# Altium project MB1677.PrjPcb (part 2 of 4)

## Sheet Arduino.SchDoc: Arduino
size A4; Date: Not used; ApprovedBy: Not used; CheckedBy: Not used; Author: Not used; CompanyName: STMicroelectronics; DrawnBy: Not used; Engineer: Not used; Organization: Not used; Address1: Not used; Address2: Not used; Address3: Not used; Address4: Not used; DocumentNumber: 11; Revision: Not used; SheetNumber: 11; SheetTotal: 15
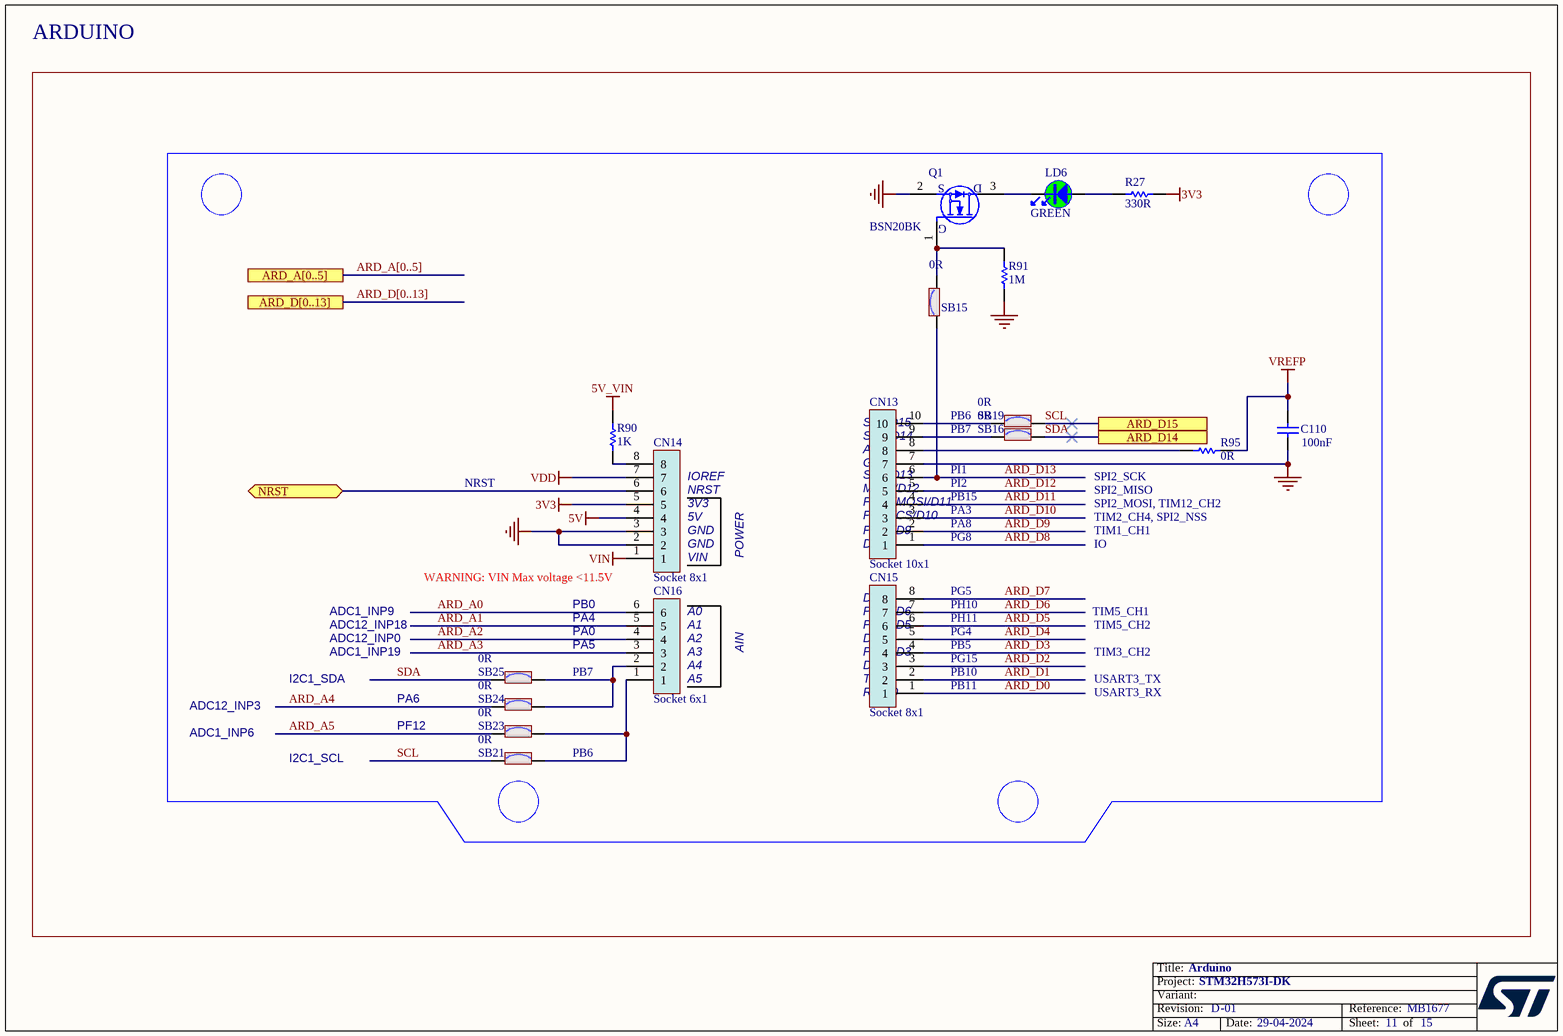
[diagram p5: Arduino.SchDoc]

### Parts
C110  value 100nF  [C0402]  (hidden comment: Capacitor)
CN13  Socket 10x1  [CON_SAMTEC_SSM-110-L-SV]
CN14  Socket 8x1  [CON_SAMTEC_SSM-108-L-SV]
CN15  Socket 8x1  [CON_SAMTEC_SSM-108-L-SV]
CN16  Socket 6x1  [CON_SAMTEC_SSM-106-L-SV]
LD6  value GREEN  [LED_0603_OSRAM_LG-Q396-PS-35_GREEN_1A2K_H0P4]  (hidden comment: LED_green)
Q1  value BSN20BK  [MOS_SOT23]  (hidden comment: BSN20)
R27  value 330R  [R0402]  (hidden comment: Resistor)
R90  value 1K  [R0402]  (hidden comment: Resistor)
R91  value 1M  [R0402]  (hidden comment: Resistor)
R95  value 0R  [R0402]  (hidden comment: Resistor)
SB15  value 0R  [SOLDER-BRIDGE_R0603-0R]  (hidden comment: SB_ON)
SB16  value 0R  [SOLDER-BRIDGE_R0603-0R]  (hidden comment: SB_ON)
SB19  value 0R  [SOLDER-BRIDGE_R0603-0R]  (hidden comment: SB_ON)
SB21  value 0R  [SOLDER-BRIDGE_R0603-0R]  (hidden comment: SB_ON)
SB23  value 0R  [SOLDER-BRIDGE_R0603-0R]  (hidden comment: SB_ON)
SB24  value 0R  [SOLDER-BRIDGE_R0603-0R]  (hidden comment: SB_ON)
SB25  value 0R  [SOLDER-BRIDGE_R0603-0R]  (hidden comment: SB_ON)

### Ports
ARD_A[0..5], ARD_D14, ARD_D15, ARD_D[0..13], NRST (bidir)

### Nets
3V3: CN14.5 R27.2
5V: CN14.4
5V_VIN: R90.2
GND: C110.2 CN13.7 CN14.2 CN14.3 Q1.2(S) R91.1
VDD: CN14.7
VIN: CN14.1
VREFP: C110.1 R95.2
ARD_A0: CN16.6
ARD_A1: CN16.5
ARD_A2: CN16.4
ARD_A3: CN16.3
ARD_A4: SB24.1
ARD_A5: SB23.1
ARD_D0: CN15.1
ARD_D1: CN15.2
ARD_D2: CN15.3
ARD_D3: CN15.4
ARD_D4: CN15.5
ARD_D5: CN15.6
ARD_D6: CN15.7
ARD_D7: CN15.8
ARD_D8: CN13.1
ARD_D9: CN13.2
ARD_D10: CN13.3
ARD_D11: CN13.4
ARD_D12: CN13.5
ARD_D13: CN13.6 SB15.1
NRST: CN14.6 ; port NRST
SCL: SB19.2 SB21.1 ; port ARD_D15
SDA: SB16.2 SB25.1 ; port ARD_D14
NetCN13_8: CN13.8 R95.1
NetCN13_9: CN13.9 SB16.1
NetCN13_10: CN13.10 SB19.1
NetCN14_8: CN14.8 R90.1
NetCN16_1: CN16.1 SB21.2 SB23.2
NetCN16_2: CN16.2 SB24.2 SB25.2
NetLD6_1: LD6.1 R27.1
NetLD6_2: LD6.2 Q1.3(D)
NetQ1_1: Q1.1(G) R91.2 SB15.2

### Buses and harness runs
bus ARD_A[0..5] = port ARD_A[0..5]
bus ARD_D[0..13] = port ARD_D[0..13]

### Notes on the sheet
- ARDUINO
- (near CN13) SDA/D14
- (near CN13) SCL/D15
- PB6
- PB7
- NRST
- (near CN14) IOREF
- (near CN14) NRST
- (near CN14) 3V3
- (near CN14) 5V
- (near CN13) PWM/CS/D10
- (near CN13) SCK/D13
- (near CN13) MISO/D12
- (near CN13) PWM/MOSI/D11
- (near CN13) AVDD
- (near CN13) GND
- PA3
- PI1
- PI2
- PB15
- TIM2_CH4, SPI2_NSS
- (near R95) SPI2_MOSI, TIM12_CH2
- SPI2_SCK
- SPI2_MISO
- WARNING: VIN Max voltage <11.5V
- (near CN14) GND
- (near CN14) VIN
- POWER
- (near CN13) D8
- (near CN13) PWM/D9
- PG8
- PA8
- TIM1_CH1
- IO
- ADC12_INP0
- ADC1_INP19
- ADC1_INP9
- ADC12_INP18
- PA5
- PA0
- PA4
- PB0
- (near CN16) A0
- (near CN16) A1
- (near CN16) A2
- (near CN16) A3
- AIN
- (near CN15) D4
- (near CN15) PWM/D3
- (near CN15) PWM/D5
- (near CN15) PWM/D6
- (near CN15) D7
- PB5
- PH10
- PG4
- PG5
- PH11
- TIM5_CH1
- TIM5_CH2
- TIM3_CH2
- ADC12_INP3
- I2C1_SDA
- PA6
- (near CN16) A4
- (near CN16) A5
- (near CN15) RX/D0
- (near CN15) TX/D1
- (near CN15) D2
- PG15
- PB11
- PB10
- USART3_TX
- USART3_RX
- ADC1_INP6
- I2C1_SCL
- PF12

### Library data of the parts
C110 = MCD-00006: Capacitor, MLCC, 100nF, 16V, X7R, +/-10%, 0402, T=0.5mm; Manufacturer_Part_Number: CC0402KRX7R7BB104; Manufacturer: YAGEO; Part_Preference: Recommended; Partial_Alternate_Internal_Part_Number: MCD-03299; Component_Country_Of_Origin: China; ID: 2474; Order_Code_RS: 9402047; ShowFields: YES
CN13 = MCD-02342: Socket, 10x1, 2.54mm, VR, SMD, T=7.37mm; Part_Type: Connector; Part_Preference: Recommended; Manufacturer: SAMTEC; Manufacturer_Part_Number: SSM-110-L-SV; Order_Code_RS: 765-5420; Component_Country_Of_Origin: China, Costa Rica, Malaysia, USA, Vietnam; ShowFields: YES; ID: 4448
CN14 CN15 = MCD-02345: Socket, 8x1, 2.54mm, VR, SMD, T=7.37mm; Part_Type: Connector; Part_Preference: Recommended; Manufacturer: SAMTEC; Manufacturer_Part_Number: SSM-108-L-SV; Order_Code_RS: 765-5411; Component_Country_Of_Origin: China, Costa Rica, Malaysia, USA, Vietnam; ShowFields: YES; ID: 4451
CN16 = MCD-02346: Socket, 6x1, 2.54mm, VR, SMD, T=7.37mm; Part_Type: Connector; Part_Preference: Recommended; Manufacturer: SAMTEC; Manufacturer_Part_Number: SSM-106-L-SV; Order_Code_RS: 765-5408; Component_Country_Of_Origin: China, Costa Rica, Malaysia, USA, Vietnam; ShowFields: YES; ID: 4452
LD6 = MCD-00588: LED Green, 0603 SMD, Forward Voltage Typ=2V, Max=2.5V; Part_Type: Display; Manufacturer_Part_Number: LG Q396-PS-35; Manufacturer: OSRAM OPTO SEMICONDUCTORS; Alternate_Manufacturer_Part_Number: VLMTG1300-GS08; Alternate_Manufacturer: VISHAY SEMICONDUCTOR OPTO DIVISION; Part_Preference: Recommended; Partial_Alternate_Internal_Part_Number: MCD-02400, MCD-03155; Provided_By: SUBCO; Component_Country_Of_Origin: Unknown; ID: 3155; ShowFields: YES
Q1 = MCD-01969: Transistor, N-channel enhancement mode field-effect transistor; Part_Preference: Recommended; Manufacturer: NEXPERIA; Order_Code_RS: 136-4845; Component_Country_Of_Origin: China; ID: 4069; ShowFields: YES
R27 = MCD-00062: Resistor,330R,0402,1%,1/16W; Manufacturer_Part_Number: RC0402FR-07330RL; Manufacturer: YAGEO; Part_Preference: Recommended; Provided_By: SUBCO; Component_Country_Of_Origin: China; ID: 2529; Order_Code_RS: 9239170; ShowFields: YES
R90 = MCD-00061: Resistor,1K,0402,1%,1/16W; Manufacturer_Part_Number: RC0402FR-071KL; Manufacturer: YAGEO; Part_Preference: Recommended; Provided_By: SUBCO; Component_Country_Of_Origin: China; ID: 2532; Order_Code_RS: 9239235; ShowFields: YES
R91 = MCD-00182: Resistor,1M,0402,1%,1/16W; Manufacturer_Part_Number: RC0402FR-071ML; Manufacturer: YAGEO; BMS_Part_Number: 9131778; Part_Preference: Recommended; Provided_By: SUBCO; Component_Country_Of_Origin: China; ID: 2686; Order_Code_RS: 618-6194; ShowFields: YES
R95 = MCD-00052: Resistor,0R,0402,5%,1/16W; Manufacturer_Part_Number: RC0402JR-070RL; Manufacturer: YAGEO; Part_Preference: Recommended; Provided_By: SUBCO; Component_Country_Of_Origin: China; ID: 2540; Order_Code_RS: 9232516RL; ShowFields: YES
SB15 SB16 SB19 SB21 SB23-SB25 = MCD-00071: Resistor, 0R, SB0603, 5%, 0.1W; Manufacturer_Part_Number: RC0603JR-070RL; Manufacturer: YAGEO; Manufacturer_HQ_COO: Unknown; Part_Preference: Recommended; Component_Country_Of_Origin: China; ID: 2521; Order_Code_RS: 199-5647; ShowFields: YES

## Sheet JTAG.SchDoc: JTAG and TRACE
size A4; Date: Not used; ApprovedBy: Not used; CheckedBy: Not used; Author: Not used; CompanyName: STMicroelectronics; DrawnBy: Not used; Engineer: Not used; Organization: Not used; Address1: Not used; Address2: Not used; Address3: Not used; Address4: Not used; DocumentNumber: 14; Revision: Not used; SheetNumber: 14; SheetTotal: 15
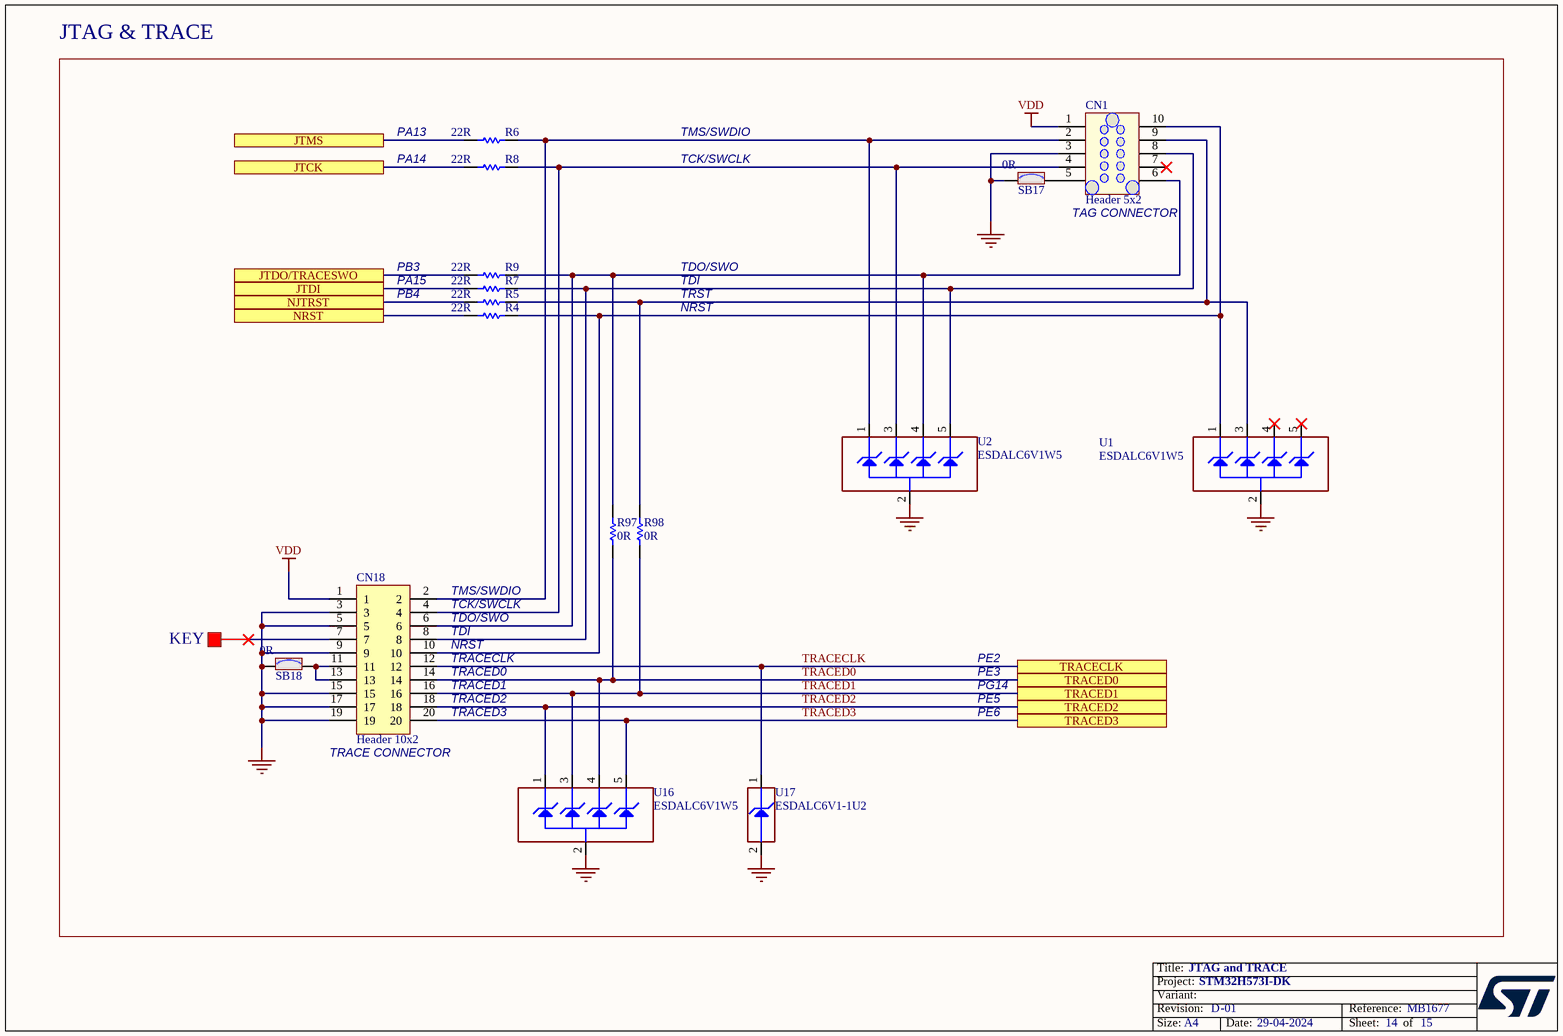
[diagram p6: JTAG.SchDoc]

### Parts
CN1  value Header 5x2  [CON_TAG-C_TC2050-IDC-NL]  (hidden comment: Tag-10-C)
CN18  Header 10x2  [CON_SAMTEC_FTSH-110-01-L-DV]
R4  value 22R  [R0603]  (hidden comment: Resistor)
R5  value 22R  [R0603]  (hidden comment: Resistor)
R6  value 22R  [R0603]  (hidden comment: Resistor)
R7  value 22R  [R0603]  (hidden comment: Resistor)
R8  value 22R  [R0603]  (hidden comment: Resistor)
R9  value 22R  [R0603]  (hidden comment: Resistor)
R97  value 0R  [R0402]  (hidden comment: Resistor)
R98  value 0R  [R0402]  (hidden comment: Resistor)
SB17  value 0R  [SOLDER-BRIDGE_R0603-0R]  (hidden comment: SB_ON)
SB18  value 0R  [SOLDER-BRIDGE_R0603-0R]  (hidden comment: SB_ON)
U1  ESDALC6V1W5  [ESD_SOT323-5L]
U2  ESDALC6V1W5  [ESD_SOT323-5L]
U16  ESDALC6V1W5  [ESD_SOT323-5L]
U17  value ESDALC6V1-1U2  [ESD_ST0201]  (hidden comment: ESD-TRANSIL)

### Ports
JTCK, JTDI, JTDO/TRACESWO, JTMS, NJTRST, NRST, TRACECLK, TRACED0, TRACED1, TRACED2, TRACED3

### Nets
GND: CN1.3 CN18.3 CN18.5 CN18.9 CN18.15 CN18.17 CN18.19 SB17.1 SB18.1 U1.2(GND) U2.2(GND) U16.2(GND) U17.2(GND)
VDD: CN1.1 CN18.1
JTCK: R8.2 ; port JTCK
JTDI: R7.2 ; port JTDI
JTDO: R9.2 ; port JTDO/TRACESWO
JTMS: R6.2 ; port JTMS
NJTRST: R5.2 ; port NJTRST
NRST: R4.2 ; port NRST
TRACECLK: CN18.12 U17.1(IO1) ; port TRACECLK
TRACED0: CN18.14 R97.1 U16.4(IO3) ; port TRACED0
TRACED1: CN18.16 R98.1 U16.3(IO2) ; port TRACED1
TRACED2: CN18.18 U16.1(IO1) ; port TRACED2
TRACED3: CN18.20 U16.5(IO4) ; port TRACED3
NetCN1_2: CN1.2 CN18.2 R6.1 U2.1(IO1)
NetCN1_4: CN1.4 CN18.4 R8.1 U2.3(IO2)
NetCN1_5: CN1.5 SB17.2
NetCN1_6: CN1.6 CN18.6 R9.1 R97.2 U2.4(IO3)
NetCN1_8: CN1.8 CN18.8 R7.1 U2.5(IO4)
NetCN1_9: CN1.9 R5.1 R98.2 U1.3(IO2)
NetCN1_10: CN1.10 CN18.10 R4.1 U1.1(IO1)
NetCN18_11: CN18.11 CN18.13 SB18.2

Not connected (* = marked no-connect by the designer): CN1 7*; CN18 7*; U1 4(IO3)* 5(IO4)*

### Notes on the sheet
- JTAG & TRACE
- PA13
- PA14
- TMS/SWDIO
- TCK/SWCLK
- TAG CONNECTOR
- PB3
- PA15
- PB4
- TDO/SWO
- TDI
- TRST
- NRST
- KEY
- (near CN18) TMS/SWDIO
- (near CN18) TCK/SWCLK
- (near CN18) TDO/SWO
- (near CN18) TDI
- (near CN18) NRST
- (near CN18) TRACECLK
- (near CN18) TRACED0
- (near CN18) TRACED1
- (near CN18) TRACED2
- (near CN18) TRACED3
- PE2
- PE3
- PG14
- PE5
- PE6
- (near CN18) TRACE CONNECTOR

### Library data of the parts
CN1 = MCD-00031: Tag_Connector Header, 10x2, No legs; Part_Preference: Recommended; Provided_By: SUBCO; ID: 2486; ShowFields: YES
CN18 = MCD-00557: Header, 10x2, 1.27mm, VR, SMD, T=3.05mm; BMS_Part_Number: 9183690; Part_Type: Connector; Part_Preference: Recommended; Manufacturer: SAMTEC; Manufacturer_Part_Number: FTSH-110-01-L-DV; Order_Code_RS: 767-6774; Component_Country_Of_Origin: China, Costa Rica, Malaysia, USA, Vietnam; ShowFields: YES; ID: 3188
R4-R9 = MCD-00066: Resistor,22R,0603,1%,1/10W; Manufacturer_Part_Number: RC0603FR-0722RL; Manufacturer: YAGEO; Part_Preference: Recommended; Provided_By: SUBCO; Component_Country_Of_Origin: China; ID: 2530; Order_Code_RS: 9238280; ShowFields: YES
R97 R98 = MCD-00052: Resistor, 0R, 0402, +/-5%, 1/16W; Part_Preference: Recommended; Manufacturer: YAGEO; Manufacturer_Part_Number: RC0402JR-070RL; Order_Code_RS: 9232516RL; Component_Country_Of_Origin: China; ID: 2540; ShowFields: YES
SB17 SB18 = MCD-00071: as SB15 on sheet Arduino
U1 U2 U16 = MCD-00136: Dual Transil array for ESD protection; Part_Type: Diode; Manufacturer: STMICROELECTRONICS; BMS_Part_Number: 9151112; Manufacturer_HQ_COO: EU; Part_Preference: Recommended; Provided_By: SUBCO with ST control; Component_Country_Of_Origin: China; ID: 2731; Order_Code_RS: 178-7373; ShowFields: YES
U17 = MCD-00170: ESD protection 6V1; BMS_Part_Number: 9151132; Part_Type: Diode; Part_Preference: Recommended; Manufacturer: STMICROELECTRONICS; Manufacturer_HQ_COO: EU; Component_Country_Of_Origin: China; ShowFields: YES; ID: 2696; Order_Code_RS: 795-8404

## Sheet Ethernet.SchDoc: Ethernet
size A4; Date: Not used; ApprovedBy: Not used; CheckedBy: Not used; Author: Not used; CompanyName: STMicroelectronics; DrawnBy: Not used; Engineer: Not used; Organization: Not used; Address1: Not used; Address2: Not used; Address3: Not used; Address4: Not used; DocumentNumber: 9; Revision: Not used; SheetNumber: 9; SheetTotal: 15
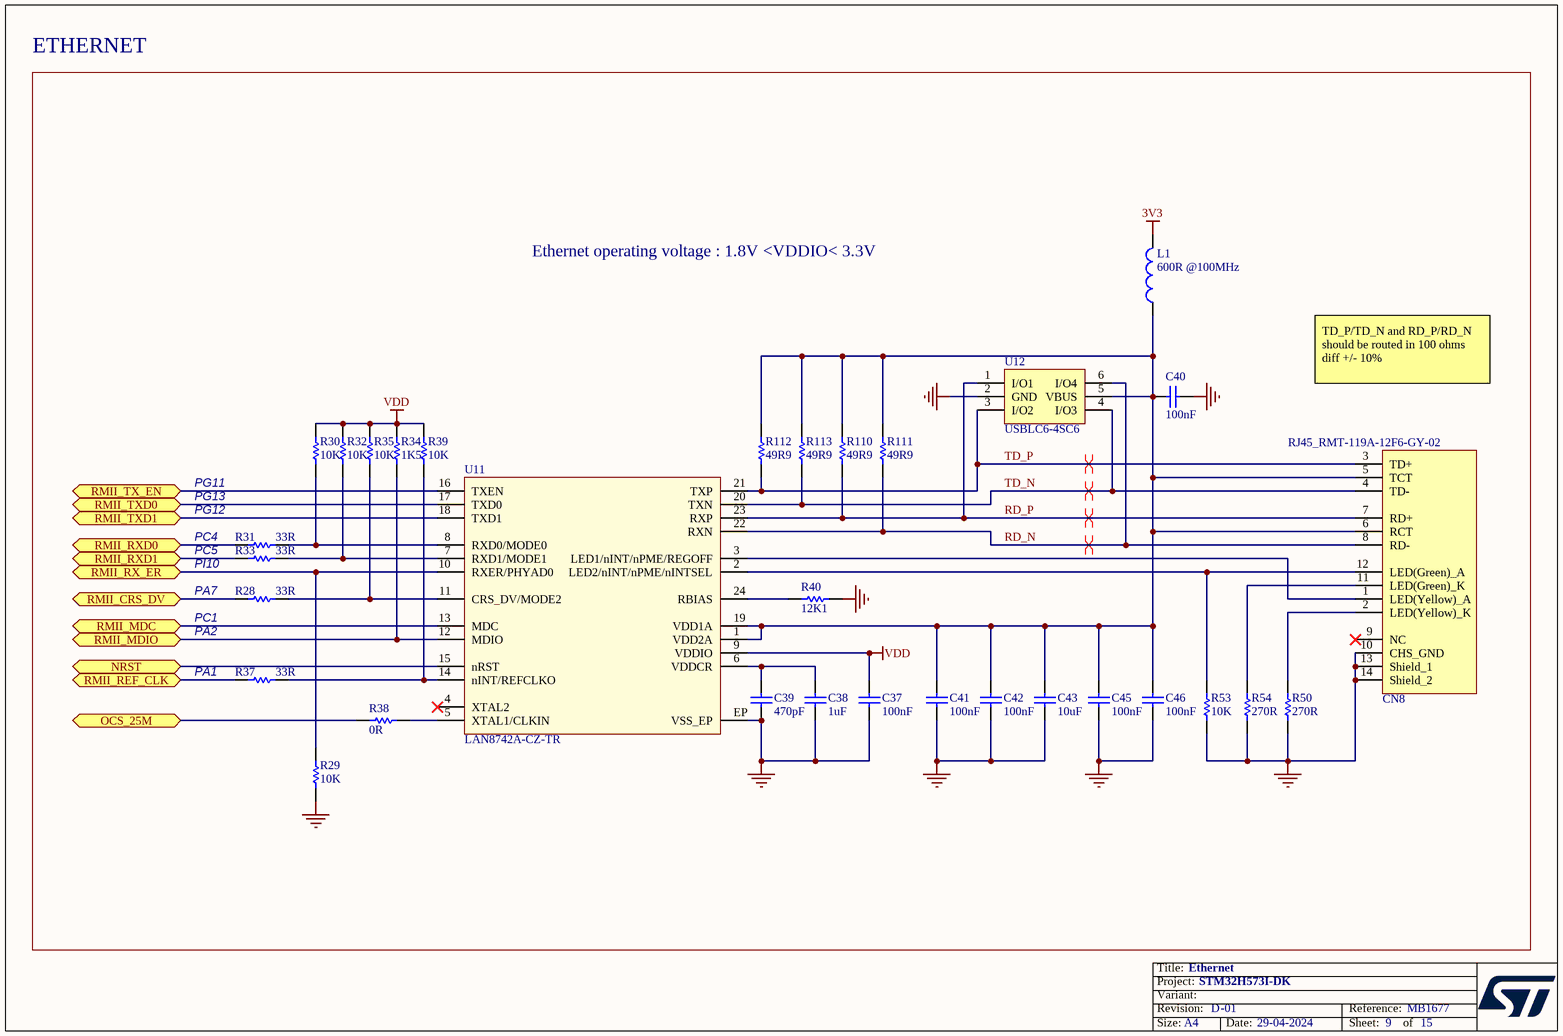
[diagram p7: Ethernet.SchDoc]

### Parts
C37  value 100nF  [C0603]  (hidden comment: Capacitor)
C38  value 1uF  [C0402]  (hidden comment: Capacitor)
C39  value 470pF  [C0402]  (hidden comment: Capacitor)
C40  value 100nF  [C0603]  (hidden comment: Capacitor)
C41  value 100nF  [C0603]  (hidden comment: Capacitor)
C42  value 100nF  [C0603]  (hidden comment: Capacitor)
C43  value 10uF  [C0603]  (hidden comment: Capacitor)
C45  value 100nF  [C0603]  (hidden comment: Capacitor)
C46  value 100nF  [C0603]  (hidden comment: Capacitor)
CN8  value RJ45_RMT-119A-12F6-GY-02  [CON_RJ45_PHC_RMT-119A-12F6-GY-02]  (hidden comment: RJ45_RTS-119A-12F6-GY-02)
L1  value 600R @100MHz  [L0603]  (hidden comment: BEAD)
R28  value 33R  [R0402]  (hidden comment: Resistor)
R29  value 10K  [R0402]  (hidden comment: Resistor)
R30  value 10K  [R0402]  (hidden comment: Resistor)
R31  value 33R  [R0402]  (hidden comment: Resistor)
R32  value 10K  [R0402]  (hidden comment: Resistor)
R33  value 33R  [R0402]  (hidden comment: Resistor)
R34  value 1K5  [R0402]  (hidden comment: Resistor)
R35  value 10K  [R0402]  (hidden comment: Resistor)
R37  value 33R  [R0402]  (hidden comment: Resistor)
R38  value 0R  [R0402]  (hidden comment: Resistor)
R39  value 10K  [R0402]  (hidden comment: Resistor)
R40  value 12K1  [R0402]  (hidden comment: Resistor)
R50  value 270R  [R0402]  (hidden comment: Resistor)
R53  value 10K  [R0402]  (hidden comment: Resistor)
R54  value 270R  [R0402]  (hidden comment: Resistor)
R110  value 49R9  [R0402]  (hidden comment: Resistor)
R111  value 49R9  [R0402]  (hidden comment: Resistor)
R112  value 49R9  [R0402]  (hidden comment: Resistor)
R113  value 49R9  [R0402]  (hidden comment: Resistor)
U11  LAN8742A-CZ-TR  [ICC_VQFN24-EPAD_4X4_P050]
U12  USBLC6-4SC6  [ESD_SOT23-6L]

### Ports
NRST (bidir), OCS_25M (bidir), RMII_CRS_DV (bidir), RMII_MDC (bidir), RMII_MDIO (bidir), RMII_REF_CLK (bidir), RMII_RX_ER (bidir), RMII_RXD0 (bidir), RMII_RXD1 (bidir), RMII_TX_EN (bidir), RMII_TXD0 (bidir), RMII_TXD1 (bidir)

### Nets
3V3: L1.2
GND: C37.1 C38.1 C39.1 C40.2 C41.1 C42.1 C43.1 C45.1 C46.1 CN8.10(CHS_GND) CN8.13(Shield_1) CN8.14(Shield_2) R29.2 R40.2 R50.1 R53.1 R54.1 U11.EP(VSS_EP) U12.2(GND)
VDD: C37.2 R30.2 R32.2 R34.2 R35.2 R39.2 U11.9(VDDIO)
NRST: U11.15(nRST) ; port NRST
OCS_25M: R38.2 ; port OCS_25M
RD_N: CN8.8(RD-) R111.1 U11.22(RXN) U12.6(I/O4)
RD_P: CN8.7(RD+) R110.1 U11.23(RXP) U12.1(I/O1)
RMII_CRS_DV: R28.1 ; port RMII_CRS_DV
RMII_MDC: U11.13(MDC) ; port RMII_MDC
RMII_MDIO: R34.1 U11.12(MDIO) ; port RMII_MDIO
RMII_REF_CLK: R37.1 ; port RMII_REF_CLK
RMII_RX_ER: R29.1 U11.10(RXER/PHYAD0) ; port RMII_RX_ER
RMII_RXD0: R31.1 ; port RMII_RXD0
RMII_RXD1: R33.1 ; port RMII_RXD1
RMII_TX_EN: U11.16(TXEN) ; port RMII_TX_EN
RMII_TXD0: U11.17(TXD0) ; port RMII_TXD0
RMII_TXD1: U11.18(TXD1) ; port RMII_TXD1
TD_N: CN8.4(TD-) R113.1 U11.20(TXN) U12.4(I/O3)
TD_P: CN8.3(TD+) R112.1 U11.21(TXP) U12.3(I/O2)
NetC38_2: C38.2 C39.2 U11.6(VDDCR)
NetC40_1: C40.1 C41.2 C42.2 C43.2 C45.2 C46.2 CN8.5(TCT) CN8.6(RCT) L1.1 R110.2 R111.2 R112.2 R113.2 U11.1(VDD2A) U11.19(VDD1A) U12.5(VBUS)
NetCN8_1: CN8.1(LED(Yellow)_A) U11.3(LED1/nINT/nPME/REGOFF)
NetCN8_2: CN8.2(LED(Yellow)_K) R50.2
NetCN8_11: CN8.11(LED(Green)_K) R54.2
NetCN8_12: CN8.12(LED(Green)_A) R53.2 U11.2(LED2/nINT/nPME/nINTSEL)
NetR28_2: R28.2 R35.1 U11.11(CRS_DV/MODE2)
NetR30_1: R30.1 R31.2 U11.8(RXD0/MODE0)
NetR32_1: R32.1 R33.2 U11.7(RXD1/MODE1)
NetR37_2: R37.2 R39.1 U11.14(nINT/REFCLKO)
NetR38_1: R38.1 U11.5(XTAL1/CLKIN)
NetR40_1: R40.1 U11.24(RBIAS)

Not connected (* = marked no-connect by the designer): CN8 9(NC)*; U11 4(XTAL2)*

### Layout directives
differential pair: RD_N, RD_P, TD_N, TD_P

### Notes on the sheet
- ETHERNET
- Ethernet operating voltage : 1.8V <VDDIO< 3.3V
- TD_P/TD_N and RD_P/RD_N should be routed in 100 ohms diff +/- 10%
- PG11
- PG13
- PG12
- PC4
- PC5
- PI10
- PA7
- (near R28) PC1
- PA2
- (near R37) PA1

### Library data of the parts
C37 C40-C42 C45 C46 = MCD-02119: Capacitor, MLCC, 100nF, 6V3, X5R, +/-10%, 0603, T=0.8mm; Manufacturer_Part_Number: C0603C104K9PACTU; Manufacturer: KEMET; Part_Preference: Recommended; Component_Country_Of_Origin: Mexico; ID: 4219; ShowFields: YES
C38 = MCD-00095: Capacitor, MLCC, 1uF, 25V, X5R, +/-10%, 0402, T=0.5mm; Manufacturer_Part_Number: GRM155R61E105KA12; Manufacturer: MURATA; Part_Preference: Recommended; Component_Country_Of_Origin: Japan°°; ID: 2772; Order_Code_RS: 2218855; ShowFields: YES
C39 = MCD-00724: Capacitor, MLCC, 470pF, 50V, NPO, +/-5%, 0402, T=0.5mm; Manufacturer_Part_Number: CC0402JRNPO9BN471; Manufacturer: YAGEO; Part_Preference: Recommended; Component_Country_Of_Origin: China; ID: 3023; Order_Code_RS: 199-2186; ShowFields: YES
C43 = MCD-01124: Capacitor, MLCC, 10µF, 10V, X5R, 10%, 0603, T=0.8mm; Manufacturer_Part_Number: GRM188R61A106KAAL; Manufacturer: MURATA; Part_Preference: Recommended; Provided_By: SUBCO; ECCN_US: EAR99; ECCN_EU: NEC; Component_Country_Of_Origin: Japan°°; ID: 3372; Order_Code_RS: 170-6258; ShowFields: YES
CN8 = MCD-02475: connector_RJ45, 10/100 Ethernet integrated MAG with integrate Green and Yellow LED, T= 13.61mm; Part_Preference: Recommended; Manufacturer: PENGHUI; Manufacturer_Part_Number: RMT-119A-12F6-GY-02; Component_Country_Of_Origin: China; ID: 4581; ShowFields: YES
L1 = MCD-02437: Ferrite bead, 600R@100MHz, +/-25%, 500mA, 380mR, 0603, T=0.8mm; Part_Type: Inductor; Part_Preference: Recommended; Manufacturer: MURATA; Manufacturer_Part_Number: BLM18AG601SN1D; Order_Code_RS: 724-1299; Component_Country_Of_Origin: Japan°; ID: 4543; ShowFields: YES
R28 R31 R33 R37 = MCD-00455: Resistor,33R,0402,1%,1/16W; Manufacturer_Part_Number: RC0402FR-0733RL; Manufacturer: YAGEO; Part_Preference: Recommended; Provided_By: SUBCO; ECCN_US: EAR99; ECCN_EU: NEC; Component_Country_Of_Origin: China; ID: 2821; ShowFields: YES
R29 R30 R32 R35 R39 R53 = MCD-00053: Resistor,10K,0402,1%,1/16W; Manufacturer_Part_Number: RC0402FR-0710KL; Manufacturer: YAGEO; BMS_Part_Number: 9131590; Part_Preference: Recommended; Provided_By: SUBCO; ECCN_US: EAR99; ECCN_EU: NEC; Component_Country_Of_Origin: China; ID: 2539; Order_Code_RS: 9239359; ShowFields: YES
R34 = MCD-00068: Resistor,1K5,0402,1%,1/16W; Manufacturer_Part_Number: RC0402FR-071K5L; Manufacturer: YAGEO; Part_Preference: Recommended; Provided_By: SUBCO; ECCN_US: EAR99; ECCN_EU: NEC; Component_Country_Of_Origin: China; ID: 2524; Order_Code_RS: 9239251; ShowFields: YES
R38 = MCD-00052: Resistor,0R,0402,5%,1/16W; Manufacturer_Part_Number: RC0402JR-070RL; Manufacturer: YAGEO; Part_Preference: Recommended; Provided_By: SUBCO; ECCN_US: EAR99; ECCN_EU: NEC; Component_Country_Of_Origin: China; ID: 2540; Order_Code_RS: 9232516RL; ShowFields: YES
R40 = MCD-00723: Resistor,12K1,0402,1%,1/16W; Manufacturer_Part_Number: RC0402FR-0712K1L; Manufacturer: YAGEO; Part_Preference: Recommended; Provided_By: SUBCO; ECCN_US: EAR99; ECCN_EU: NEC; Component_Country_Of_Origin: China; ID: 3022; ShowFields: YES
R50 R54 = MCD-00441: Resistor,270R,0402,1%,1/16W; Manufacturer_Part_Number: RC0402FR-07270RL; Manufacturer: YAGEO; Part_Preference: Recommended; Provided_By: SUBCO; ECCN_US: EAR99; ECCN_EU: NEC; Component_Country_Of_Origin: China; ID: 2838; ShowFields: YES
R110-R113 = MCD-00565: Resistor,49R9,0402,1%,1/16W; Manufacturer_Part_Number: RC0402FR-0749R9L; Manufacturer: YAGEO; Part_Preference: Recommended; Provided_By: SUBCO; ECCN_US: EAR99; ECCN_EU: NEC; Component_Country_Of_Origin: China; ID: 3178; ShowFields: YES
U11 = MCD-00719: 10/100M RMII Ethernet transceiver; Part_Type: IC; Manufacturer: MICROCHIP; BMS_Part_Number: 9177984; Part_Preference: Recommended; Partial_Alternate_Internal_Part_Number: MCD-03200; Provided_By: SUBCO; Component_Country_Of_Origin: Unknown; ID: 3026; Order_Code_RS: 215-3925; ShowFields: YES
U12 = MCD-00250: Very low capacitance ESD protection , 4 lines; Part_Type: Diode; Manufacturer: STMICROELECTRONICS; BMS_Part_Number: 9151001; Part_Preference: Recommended; Provided_By: SUBCO with ST control; ECCN_US: EAR99; ECCN_EU: NEC; Component_Country_Of_Origin: China; ID: 2616; Order_Code_RS: 920-6272; ShowFields: YES

## Sheet STLINK_V3EC.SchDoc: STLINK-V3EC
size A3; Date: Not used; ApprovedBy: Not used; CheckedBy: Not used; Author: Not used; CompanyName: STMicroelectronics; DrawnBy: Not used; Engineer: Not used; Organization: Not used; Address1: Not used; Address2: Not used; Address3: Not used; Address4: Not used; DocumentNumber: 15; Revision: Not used; SheetNumber: 15; SheetTotal: 15
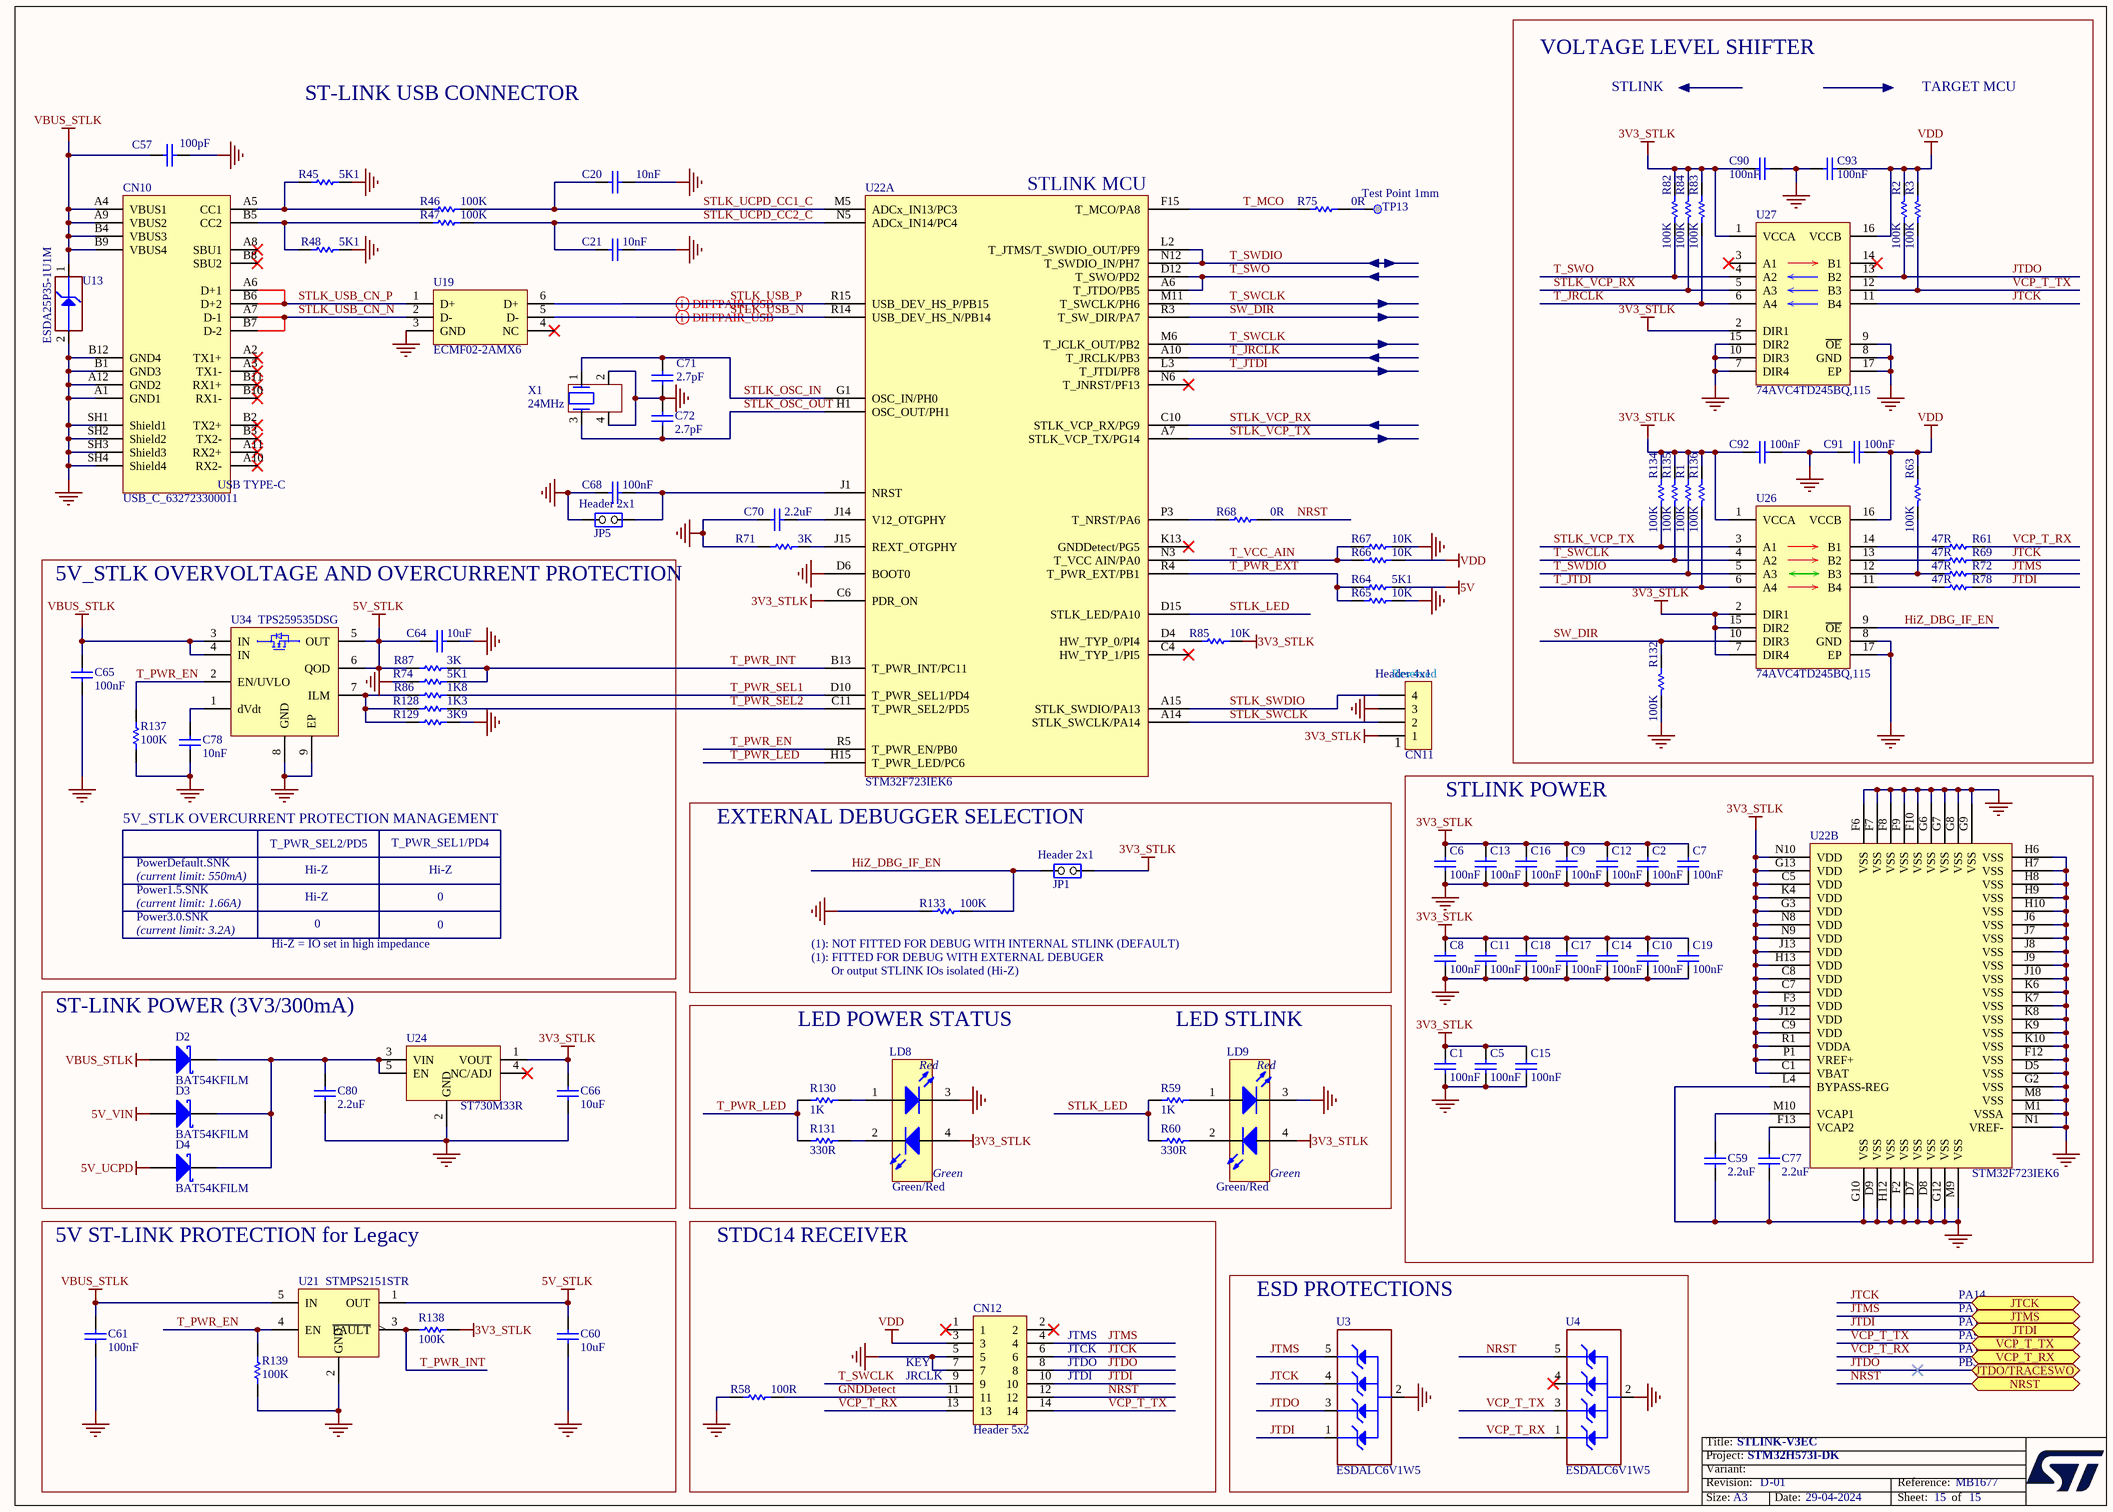
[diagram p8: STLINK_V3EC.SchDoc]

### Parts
C1  value 100nF  [C0402]  (hidden comment: Capacitor)
C2  value 100nF  [C0402]  (hidden comment: Capacitor)
C5  value 100nF  [C0402]  (hidden comment: Capacitor)
C6  value 100nF  [C0402]  (hidden comment: Capacitor)
C7  value 100nF  [C0402]  (hidden comment: Capacitor)
C8  value 100nF  [C0402]  (hidden comment: Capacitor)
C9  value 100nF  [C0402]  (hidden comment: Capacitor)
C10  value 100nF  [C0402]  (hidden comment: Capacitor)
C11  value 100nF  [C0402]  (hidden comment: Capacitor)
C12  value 100nF  [C0402]  (hidden comment: Capacitor)
C13  value 100nF  [C0402]  (hidden comment: Capacitor)
C14  value 100nF  [C0402]  (hidden comment: Capacitor)
C15  value 100nF  [C0402]  (hidden comment: Capacitor)
C16  value 100nF  [C0402]  (hidden comment: Capacitor)
C17  value 100nF  [C0402]  (hidden comment: Capacitor)
C18  value 100nF  [C0402]  (hidden comment: Capacitor)
C19  value 100nF  [C0402]  (hidden comment: Capacitor)
C20  value 10nF  [C0402]  (hidden comment: Capacitor)
C21  value 10nF  [C0402]  (hidden comment: Capacitor)
C57  value 100pF  [C0402]  (hidden comment: Capacitor)
C59  value 2.2uF  [C0402]  (hidden comment: Capacitor)
C60  value 10uF  [C0603]  (hidden comment: Capacitor)
C61  value 100nF  [C0402]  (hidden comment: Capacitor)
C64  value 10uF  [C0603]  (hidden comment: Capacitor)
C65  value 100nF  [C0402]  (hidden comment: Capacitor)
C66  value 10uF  [C0603]  (hidden comment: Capacitor)
C68  value 100nF  [C0402]  (hidden comment: Capacitor)
C70  value 2.2uF  [C0402]  (hidden comment: Capacitor)
C71  value 2.7pF  [C0402]  (hidden comment: Capacitor)
C72  value 2.7pF  [C0402]  (hidden comment: Capacitor)
C77  value 2.2uF  [C0402]  (hidden comment: Capacitor)
C78  value 10nF  [C0402]  (hidden comment: Capacitor)
C80  value 2.2uF  [C0805]  (hidden comment: Capacitor)
C90  value 100nF  [C0402]  (hidden comment: Capacitor)
C91  value 100nF  [C0402]  (hidden comment: Capacitor)
C92  value 100nF  [C0402]  (hidden comment: Capacitor)
C93  value 100nF  [C0402]  (hidden comment: Capacitor)
CN10  value USB_C_632723300011  [CON_USB-TYPEC_WE_632723300011]  (hidden comment: USB_TYPE_C_Receptacle)
CN11  Header 4x1  [CON_SAMTEC_TSW-104-07-G-S]
CN12  value Header 5x2  [CON_STDC14_Receiver_MEDIUM_WITH_MIPI10_3D]  (hidden comment: Header 7x2)
D2  value BAT54KFILM  [DIO_SOD523_1A_2K]  (hidden comment: SCHOTTKY_1A_2K)
D3  value BAT54KFILM  [DIO_SOD523_1A_2K]  (hidden comment: SCHOTTKY_1A_2K)
D4  value BAT54KFILM  [DIO_SOD523_1A_2K]  (hidden comment: SCHOTTKY_1A_2K)
JP1  value Header 2x1  [CON_SAMTEC_TSW-102-07-G-S]  (hidden comment: Jumper_Header 2x1)
JP5  value Header 2x1  [CON_SAMTEC_TSW-102-07-G-S]  (hidden comment: Jumper_Header 2x1)
LD8  value Green/Red  [LED_BI-GR_WE-150141SV73110]  (hidden comment: LED_BICOLOR)
LD9  value Green/Red  [LED_BI-GR_WE-150141SV73110]  (hidden comment: LED_BICOLOR)
R1  value 100K  [R0402]  (hidden comment: Resistor)
R2  value 100K  [R0402]  (hidden comment: Resistor)
R3  value 100K  [R0402]  (hidden comment: Resistor)
R45  value 5K1  [R0402]  (hidden comment: Resistor)
R46  value 100K  [R0402]  (hidden comment: Resistor)
R47  value 100K  [R0402]  (hidden comment: Resistor)
R48  value 5K1  [R0402]  (hidden comment: Resistor)
R58  value 100R  [R0402]  (hidden comment: Resistor)
R59  value 1K  [R0402]  (hidden comment: Resistor)
R60  value 330R  [R0402]  (hidden comment: Resistor)
R61  value 47R  [R0402]  (hidden comment: Resistor)
R63  value 100K  [R0402]  (hidden comment: Resistor)
R64  value 5K1  [R0402]  (hidden comment: Resistor)
R65  value 10K  [R0402]  (hidden comment: Resistor)
R66  value 10K  [R0402]  (hidden comment: Resistor)
R67  value 10K  [R0402]  (hidden comment: Resistor)
R68  value 0R  [R0402]  (hidden comment: Resistor)
R69  value 47R  [R0402]  (hidden comment: Resistor)
R71  value 3K  [R0402]  (hidden comment: Resistor)
R72  value 47R  [R0402]  (hidden comment: Resistor)
R74  value 5K1  [R0402]  (hidden comment: Resistor)
R75  value 0R  [R0402]  (hidden comment: Resistor)
R78  value 47R  [R0402]  (hidden comment: Resistor)
R82  value 100K  [R0402]  (hidden comment: Resistor)
R83  value 100K  [R0402]  (hidden comment: Resistor)
R84  value 100K  [R0402]  (hidden comment: Resistor)
R85  value 10K  [R0402]  (hidden comment: Resistor)
R86  value 1K8  [R0402]  (hidden comment: Resistor)
R87  value 3K  [R0402]  (hidden comment: Resistor)
R128  value 1K3  [R0402]  (hidden comment: Resistor)
R129  value 3K9  [R0402]  (hidden comment: Resistor)
R130  value 1K  [R0402]  (hidden comment: Resistor)
R131  value 330R  [R0402]  (hidden comment: Resistor)
R132  value 100K  [R0402]  (hidden comment: Resistor)
R133  value 100K  [R0402]  (hidden comment: Resistor)
R134  value 100K  [R0402]  (hidden comment: Resistor)
R135  value 100K  [R0402]  (hidden comment: Resistor)
R136  value 100K  [R0402]  (hidden comment: Resistor)
R137  value 100K  [R0402]  (hidden comment: Resistor)
R138  value 100K  [R0402]  (hidden comment: Resistor)
R139  value 100K  [R0402]  (hidden comment: Resistor)
TP13  value Test Point 1mm  [TP_SMD_1MM]  (hidden comment: Test Point)  (no BOM)
U3  ESDALC6V1W5  [ESD_SOT323-5L]
U4  ESDALC6V1W5  [ESD_SOT323-5L]
U13  value ESDA25P35-1U1M  [ESD_QFN1610_2N_1K_2A]  (hidden comment: ESD-TRANSIL)
U19  ECMF02-2AMX6  [ESD_QFN-6L_1P7X1P5_P050]
U21  STMPS2151STR  [MOS_SOT23-5L]
U22  value STM32F723IEK6  [ICC_UFBGA201_176+25_10X10_P065]  (hidden comment: STLINK-V3EC)  (parts A,B of 2)
U24  ST730M33R  [ICC_SOT23-5L_H1P45]
U26  value 74AVC4TD245BQ,115  [ICC_DHVQFN16-EPAD_SOT763-1_2P5X3P5_H0P85_P050]  (hidden comment: 74AVC4TD245BQ)
U27  value 74AVC4TD245BQ,115  [ICC_DHVQFN16-EPAD_SOT763-1_2P5X3P5_H0P85_P050]  (hidden comment: 74AVC4TD245BQ)
U34  TPS259535DSG  [ICC_WSON8-EPAD_2X2_P050]
X1  value 24MHz  [CRY_NX2016SA_4P]  (hidden comment: XTAL_4_PINS)

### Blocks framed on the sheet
VOLTAGE LEVEL SHIFTER: C90-C93 R1-R3 R61 R63 R69 R72 R78 R82-R84 R132 R134-R136 U26 U27
5V_STLK OVERVOLTAGE AND OVERCURRENT PROTECTION: C64 C65 C78 R74 R86 R87 R128 R129 R137 U34
STLINK POWER: C1 C2 C5-C19 C59 C77 U22
EXTERNAL DEBUGGER SELECTION: JP1 R133
ST-LINK POWER (3V3/300mA): C66 C80 D2-D4 U24
5V ST-LINK PROTECTION for Legacy: C60 C61 R138 R139 U21
STDC14 RECEIVER: CN12 R58
ESD PROTECTIONS: U3 U4

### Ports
JTCK (bidir), JTDI (bidir), JTDO/TRACESWO (bidir), JTMS (bidir), NRST (bidir), VCP_T_RX (bidir), VCP_T_TX (bidir)

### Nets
3V3_STLK: C1.1 C2.1 C5.1 C6.1 C7.1 C8.1 C9.1 C10.1 C11.1 C12.1 C13.1 C14.1 C15.1 C16.1 C17.1 C18.1 C19.1 C66.2 C90.2 C92.2 CN11.1 JP1.1(COMMON) LD8.4(Green_anode) LD9.4(Green_anode) R1.2 R82.2 R83.2 R84.2 R85.2 R134.1 R135.2 R136.2 R138.1 U22.C1(VBAT) U22.C5(VDD) U22.C6(PDR_ON) U22.C7(VDD) U22.C8(VDD) U22.C9(VDD) U22.F3(VDD) U22.G3(VDD) U22.G13(VDD) U22.H13(VDD) U22.J12(VDD) U22.J13(VDD) U22.K4(VDD) U22.N8(VDD) U22.N9(VDD) U22.N10(VDD) U22.P1(VREF+) U22.R1(VDDA) U24.1(VOUT) U26.1(VCCA) U26.2(DIR1) U26.7(DIR4) U26.15(DIR2) U27.1(VCCA) U27.2(DIR1)
5V: R64.2
5V_STLK: C60.2 C64.2 R87.1 U21.1(OUT) U34.5(OUT) U34.6(QOD)
5V_UCPD: D4.1(A)
5V_VIN: D3.1(A)
GND: C1.2 C2.2 C5.2 C6.2 C7.2 C8.2 C9.2 C10.2 C11.2 C12.2 C13.2 C14.2 C15.2 C16.2 C17.2 C18.2 C19.2 C20.2 C21.2 C57.2 C59.1 C60.1 C61.1 C64.1 C65.1 C66.1 C68.1 C70.1 C71.1 C72.2 C77.1 C78.1 C80.1 C90.1 C91.2 C92.1 C93.2 CN10.A1(GND1) CN10.A12(GND2) CN10.B1(GND3) CN10.B12(GND4) CN10.SH1(Shield1) CN10.SH2(Shield2) CN10.SH3(Shield3) CN10.SH4(Shield4) CN11.3 CN12.5 CN12.7 JP5.2(NO) LD8.3(RED_cathode) LD9.3(RED_cathode) R45.2 R48.2 R58.1 R65.2 R67.2 R71.2 R74.1 R129.2 R132.1 R133.1 R137.1 R139.1 U3.2(GND) U4.2(GND) U13.2(GND) U19.3(GND) U21.2(GND) U22.D5(VSS) U22.D6(BOOT0) U22.D7(VSS) U22.D8(VSS) U22.D9(VSS) U22.F2(VSS) U22.F6(VSS) U22.F7(VSS) U22.F8(VSS) U22.F9(VSS) U22.F10(VSS) U22.F12(VSS) U22.G2(VSS) U22.G6(VSS) U22.G7(VSS) U22.G8(VSS) U22.G9(VSS) U22.G10(VSS) U22.G12(VSS) U22.H6(VSS) U22.H7(VSS) U22.H8(VSS) U22.H9(VSS) U22.H10(VSS) U22.H12(VSS) U22.J6(VSS) U22.J7(VSS) U22.J8(VSS) U22.J9(VSS) U22.J10(VSS) U22.K6(VSS) U22.K7(VSS) U22.K8(VSS) U22.K9(VSS) U22.K10(VSS) U22.L4(BYPASS-REG) U22.M1(VSSA) U22.M8(VSS) U22.M9(VSS) U22.N1(VREF-) U24.2(GND) U26.8(GND) U26.17(EP) U27.7(DIR4) U27.8(GND) U27.9(~{OE}) U27.10(DIR3) U27.15(DIR2) U27.17(EP) U34.8(GND) U34.9(EP) X1.2 X1.4
VBUS_STLK: C57.1 C61.2 C65.2 CN10.A4(VBUS1) CN10.A9(VBUS2) CN10.B4(VBUS3) CN10.B9(VBUS4) D2.1(A) U13.1(IO1) U21.5(IN) U34.3(IN) U34.4(IN)
VDD: C91.1 C93.1 CN12.3 R2.2 R3.2 R63.2 R66.2 U26.16(VCCB) U27.16(VCCB)
GNDDetect: CN12.11 R58.2
HiZ_DBG_IF_EN: JP1.2(NO) R133.2 U26.9(~{OE})
JTCK: CN12.6 R69.2 U3.4(IO3) U27.11(B4) ; port JTCK
JTDI: CN12.10 R78.2 U3.1(IO1) ; port JTDI
JTDO: CN12.8 R2.1 U3.3(IO2) U27.13(B2) ; port JTDO/TRACESWO
JTMS: CN12.4 R72.2 U3.5(IO4) ; port JTMS
NRST: CN12.12 R68.2 U4.5(IO4) ; port NRST
STLK_LED: R59.2 R60.1 U22.D15(STLK_LED/PA10)
STLK_OSC_IN: C71.2 U22.G1(OSC_IN/PH0) X1.1
STLK_OSC_OUT: C72.1 U22.H1(OSC_OUT/PH1) X1.3
STLK_SWCLK: CN11.2 U22.A14(STLK_SWCLK/PA14)
STLK_SWDIO: CN11.4 U22.A15(STLK_SWDIO/PA13)
STLK_UCPD_CC1_C: C20.1 R46.2 U22.M5(ADCx_IN13/PC3)
STLK_UCPD_CC2_C: C21.1 R47.2 U22.N5(ADCx_IN14/PC4)
STLK_USB_CN_N: CN10.A7(D-1) CN10.B7(D-2) U19.2(D-)
STLK_USB_CN_P: CN10.A6(D+1) CN10.B6(D+2) U19.1(D+)
STLK_USB_N: U19.5(D-) U22.R14(USB_DEV_HS_N/PB14)
STLK_USB_P: U19.6(D+) U22.R15(USB_DEV_HS_P/PB15)
STLK_VCP_RX: R84.1 U22.C10(STLK_VCP_RX/PG9) U27.5(A3)
STLK_VCP_TX: R134.2 U22.A7(STLK_VCP_TX/PG14) U26.3(A1)
SW_DIR: R132.2 U22.R3(T_SW_DIR/PA7) U26.10(DIR3)
T_JRCLK: R83.1 U22.A10(T_JRCLK/PB3) U27.6(A4)
T_JTDI: R136.1 U22.L3(T_JTDI/PF8) U26.6(A4)
T_MCO: R75.1 U22.F15(T_MCO/PA8)
T_PWR_EN: R137.2 R139.2 U21.4(EN) U22.R5(T_PWR_EN/PB0) U34.2(EN/UVLO)
T_PWR_EXT: R64.1 R65.1 U22.R4(T_PWR_EXT/PB1)
T_PWR_INT: R74.2 R87.2 R138.2 U21.3(~{FAULT}) U22.B13(T_PWR_INT/PC11)
T_PWR_LED: R130.2 R131.2 U22.H15(T_PWR_LED/PC6)
T_PWR_SEL1: R86.2 U22.D10(T_PWR_SEL1/PD4)
T_PWR_SEL2: R128.2 U22.C11(T_PWR_SEL2/PD5)
T_SWCLK: CN12.9 R135.1 U22.M6(T_JCLK_OUT/PB2) U22.M11(T_SWCLK/PH6) U26.4(A2)
T_SWDIO: R1.1 U22.L2(T_JTMS/T_SWDIO_OUT/PF9) U22.N12(T_SWDIO_IN/PH7) U26.5(A3)
T_SWO: R82.1 U22.A6(T_JTDO/PB5) U22.D12(T_SWO/PD2) U27.4(A2)
T_VCC_AIN: R66.1 R67.1 U22.N3(T_VCC_AIN/PA0)
VCP_T_RX: CN12.13 R61.2 U4.1(IO1) ; port VCP_T_RX
VCP_T_TX: CN12.14 R3.1 U4.3(IO2) U27.12(B3) ; port VCP_T_TX
NetC59_2: C59.2 U22.M10(VCAP1)
NetC68_2: C68.2 JP5.1(COMMON) U22.J1(NRST)
NetC70_2: C70.2 U22.J14(V12_OTGPHY)
NetC77_2: C77.2 U22.F13(VCAP2)
NetC78_2: C78.2 U34.1(dVdt)
NetC80_2: C80.2 D2.2(K) D3.2(K) D4.2(K) U24.3(VIN) U24.5(EN)
NetCN10_A5: CN10.A5(CC1) R45.1 R46.1
NetCN10_B5: CN10.B5(CC2) R47.1 R48.1
NetLD8_1: LD8.1(Red_anode) R130.1
NetLD8_2: LD8.2(Green_cathode) R131.1
NetLD9_1: LD9.1(Red_anode) R59.1
NetLD9_2: LD9.2(Green_cathode) R60.2
NetR61_1: R61.1 U26.14(B1)
NetR63_1: R63.1 R72.1 U26.12(B3)
NetR68_1: R68.1 U22.P3(T_NRST/PA6)
NetR69_1: R69.1 U26.13(B2)
NetR71_1: R71.1 U22.J15(REXT_OTGPHY)
NetR75_2: R75.2 TP13.1
NetR78_1: R78.1 U26.11(B4)
NetR85_1: R85.1 U22.D4(HW_TYP_0/PI4)
NetR86_1: R86.1 R128.1 R129.1 U34.7(ILM)

Not connected (* = marked no-connect by the designer): CN10 A2(TX1+)* A3(TX1-)* A8(SBU1)* A10(RX2-)* A11(RX2+)* B2(TX2+)* B3(TX2-)* B8(SBU2)* B10(RX1-)* B11(RX1+)*; CN12 1* 2*; U4 4(IO3)*; U19 4(NC)*; U22 C4(HW_TYP_1/PI5)* K13(GNDDetect/PG5)* N6(T_JNRST/PF13)*; U24 4(NC/ADJ)*; U27 3(A1)* 14(B1)*

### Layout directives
differential pair; rule Impedance Constraint [Min = 85.00    Max = 95.00    ]: STLK_USB_N, STLK_USB_P

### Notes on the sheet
- ST-LINK USB CONNECTOR
- STLINK
- TARGET MCU
- (near U22) STLINK MCU
- (near CN11) Reserved
- (near CN11) 1
- 5V_STLK OVERCURRENT PROTECTION MANAGEMENT
- T_PWR_SEL2/PD5
- T_PWR_SEL1/PD4
- (current limit: 550mA)
- (current limit: 1.66A)
- Power1.5.SNK
- Power3.0.SNK
- PowerDefault.SNK
- Hi-Z
- 0
- (current limit: 3.2A)
- Hi-Z = IO set in high impedance
- (near R133) (1): NOT FITTED FOR DEBUG WITH INTERNAL STLINK (DEFAULT)
- (near R133) (1): FITTED FOR DEBUG WITH EXTERNAL DEBUGER
- Or output STLINK IOs isolated (Hi-Z)
- LED POWER STATUS
- LED STLINK
- PA14
- PA13
- PA15
- (near CN12) JRCLK
- (near CN12) KEY
- (near CN12) JTMS
- (near CN12) JTCK
- (near CN12) JTDO
- (near CN12) JTDI
- PA9
- PB3
- PA10

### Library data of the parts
C1 C2 C5-C19 C68 C90-C93 = MCD-00006: as C110 on sheet Arduino
C20 C21 C78 = MCD-02198: Capacitor, MLCC, 10nF, 50V, X7R, +/-10%, 0402, T=0.5mm; Part_Preference: Recommended; Manufacturer: YAGEO; Manufacturer_Part_Number: CC0402KRX7R9BB103; Order_Code_RS: 6169644; Component_Country_Of_Origin: China; ID: 4298; ShowFields: YES
C57 = MCD-00205: Capacitor, MLCC, 100pF, 50V, NPO, +/-5%, 0402, T=0.5mm; Part_Preference: Recommended; Manufacturer: YAGEO; Manufacturer_Part_Number: CC0402JRNPO9BN101; Component_Country_Of_Origin: China; ID: 2658; ShowFields: YES
C59 C70 C77 = MCD-02606: Capacitor, MLCC, 2.2uF, 6.3V, X5R, +/-10%, 0402, T=0.5mm; Part_Preference: Recommended; Manufacturer: YAGEO; Manufacturer_Part_Number: CC0402KRX5R5BB225; Order_Code_RS: 1992205; Component_Country_Of_Origin: China°; ID: 4712; ShowFields: YES
C60 = MCD-00099: Capacitor, MLCC, 10uF, 10V, X5R, +/-10%, 0603, T=0.8mm; Part_Preference: Recommended; Manufacturer: MURATA; Manufacturer_Part_Number: GRM188R61A106KE69D; Partial_Alternate_Internal_Part_Number: MCD-03152; Order_Code_RS: 2494233; Component_Country_Of_Origin: Japan°°; ShowFields: YES; ID: 2770
C61 = MCD-02355: Capacitor, MLCC, 100nF, 25V, X7R, +/-10%, 0402, T=0.5mm; Part_Preference: Recommended; Manufacturer: WALSIN TECHNOLOGY CORPORATION; Manufacturer_Part_Number: 0402B104K250CT; Partial_Alternate_Internal_Part_Number: MCD-03302, MCD-03304; Order_Code_RS: 176-3114; Component_Country_Of_Origin: Unknown; ShowFields: YES; ID: 4461
C64 C66 = MCD-00099: Capacitor, MLCC, 10uF, 10V, X5R, +/-10%, 0603, T=0.8mm; Part_Preference: Recommended; Manufacturer: MURATA; Manufacturer_Part_Number: GRM188R61A106KE69D; Partial_Alternate_Internal_Part_Number: MCD-03152; Order_Code_RS: 2494233; Component_Country_Of_Origin: Japan°°; ID: 2770; ShowFields: YES
C65 = MCD-02355: Capacitor, MLCC, 100nF, 25V, X7R, +/-10%, 0402, T=0.5mm; Part_Preference: Recommended; Manufacturer: WALSIN TECHNOLOGY CORPORATION; Manufacturer_Part_Number: 0402B104K250CT; Partial_Alternate_Internal_Part_Number: MCD-03302, MCD-03304; Order_Code_RS: 176-3114; Component_Country_Of_Origin: Unknown; ID: 4461; ShowFields: YES
C71 C72 = MCD-01774: Capacitor, MLCC, 2.7pF, 50V, NPO, +/-0.1pF, 0402, T=0.5mm; Part_Preference: Recommended; Manufacturer: YAGEO; Manufacturer_Part_Number: CC0402BRNPO9BN2R7; Component_Country_Of_Origin: China; ID: 3874; ShowFields: YES
C80 = MCD-02372: Capacitor, MLCC, 2.2uF, 25V, X7R, +/-10%, 0805, T=1,25mm; Manufacturer_Part_Number: GRM21BR71E225KE11L; Manufacturer: MURATA; Part_Preference: Recommended; ECCN_US: EAR99; ECCN_EU: NEC; Provided_By: SUBCO; Component_Country_Of_Origin: Japan°; ID: 4478; ShowFields: YES
CN10 = MCD-02273: USB_TypeC, 24pins, RA, TH, T=1.9mm (USB certified); Part_Type: Connector; Part_Preference: Recommended; Manufacturer: WURTH ELEKTRONIK; Manufacturer_Part_Number: 632723300011; Full_Alternate_Internal_Part_Number: MCD-01108; Component_Country_Of_Origin: China; ShowFields: YES; ID: 4373
CN11 = MCD-00029: Header, 4x1, 2,54mm, VR, TH, Height 5.84mm/2.54mm; Manufacturer_Part_Number: TSW-104-07-G-S; Manufacturer: SAMTEC; Part_Type: Connector; Part_Preference: Recommended; Provided_By: SUBCO; Component_Country_Of_Origin: China, Costa Rica, Malaysia, USA, Vietnam; ID: 2487; Order_Code_RS: 2667450; ShowFields: YES
CN12 = MCD-01226: Header, 5x2, 1.27mm, VR, SMD, T=5.97mm/3.05mm; Part_Type: Connector; Part_Preference: Recommended; Manufacturer: SAMTEC; Manufacturer_Part_Number: FTSH-105-01-L-DV-K; Partial_Alternate_Internal_Part_Number: MCD-02956, MCD-03788; Order_Code_RS: 159-2332; Component_Country_Of_Origin: China, Costa Rica, Malaysia, USA, Vietnam; ID: 3265; ShowFields: YES
D2-D4 = MCD-01677: Small signal Schottky diodes; BMS_Part_Number: 9151123; Part_Type: Diode; Part_Preference: Recommended; Manufacturer: STMICROELECTRONICS; Manufacturer_HQ_COO: EU; Component_Country_Of_Origin: China; ShowFields: YES; ID: 3777; Order_Code_RS: 714-6869
JP1 JP5 = MCD-00045: Header, 2x1, 2,54mm, VR, TH, Height 5.84mm/2.54mm; Part_Preference: Recommended; Part_Type: Connector; Manufacturer: SAMTEC; Manufacturer_Part_Number: TSW-102-07-G-S; Alternate_Manufacturer: JIUBABA; LIANYI; Alternate_Manufacturer_Part_Number: 313102S111116;313102S111116; Full_Alternate_Internal_Part_Number: MCD-02390; Partial_Alternate_Internal_Part_Number: MCD-02957, MCD-03720; Component_Country_Of_Origin: China, Costa Rica, Malaysia, USA, Vietnam; ID: 2545; Order_Code_RS: 2505044; ShowFields: YES
LD8 LD9 = MCD-02631: LED Bicolor, Green/Red, 2V, 20mA,  4-PLCC; Part_Type: Display; Part_Preference: Recommended; Manufacturer: WURTH ELEKTRONIK; Manufacturer_Part_Number: 150141SV73110; Order_Code_RS: 184-6963; Component_Country_Of_Origin: China; ID: 4737; ShowFields: YES
R1-R3 R63 R82-R84 R132 R134-R136 = MCD-00059: Resistor,100K,0402,1%,1/16W; Manufacturer_Part_Number: RC0402FR-07100KL; Manufacturer: YAGEO; Alternate_Manufacturer_Part_Number: RT0402FRE07100KL; Part_Preference: Recommended; Partial_Alternate_Internal_Part_Number: MCD-03301; Provided_By: Subcon; Initial_Board_Reference: MB1274; Component_Country_Of_Origin: China; ID: 2533; Order_Code_RS: 2421891; ShowFields: YES
R45 R48 R64 R74 = MCD-00333: Resistor, 5K1, 0402, +/-1%, 1/16W; Part_Preference: Recommended; Manufacturer: YAGEO; Manufacturer_Part_Number: RC0402FR-075K1L; Component_Country_Of_Origin: China; ID: 2944; ShowFields: YES
R46 R47 R133 R137-R139 = MCD-00059: Resistor, 100K, 0402, +/-1%, 1/16W; Part_Preference: Recommended; Manufacturer: YAGEO; Manufacturer_Part_Number: RC0402FR-07100KL; Partial_Alternate_Internal_Part_Number: MCD-03301; Order_Code_RS: 2421891; Component_Country_Of_Origin: China; ShowFields: YES; ID: 2533
R58 = MCD-00067: Resistor, 100R, 0402, +/- 1%, 1/16W; Part_Preference: Recommended; Manufacturer: YAGEO; Manufacturer_Part_Number: RC0402FR-07100RL; Order_Code_RS: 9239111; Component_Country_Of_Origin: China; ShowFields: YES; ID: 2527
R59 R130 = MCD-02665: Resistor, 1K, 0402, +/-0.1%, 1/16W, +/-25ppm/°C; Part_Preference: Recommended; Manufacturer: YAGEO; Manufacturer_Part_Number: RT0402BRD071KL; Order_Code_RS: 199-1298; Component_Country_Of_Origin: Taiwan; ID: 4771; ShowFields: YES
R60 R131 = MCD-00062: Resistor, 330R, 0402, +/-1%, 1/16W; Part_Preference: Recommended; Manufacturer: YAGEO; Manufacturer_Part_Number: RC0402FR-07330RL; Order_Code_RS: 9239170; Component_Country_Of_Origin: China; ID: 2529; ShowFields: YES
R61 R69 R72 R78 = MCD-00481: Resistor,47R,0402,1%,1/16W; Manufacturer_Part_Number: RC0402FR-0747RL; Manufacturer: YAGEO; Part_Preference: Recommended; Provided_By: SUBCO; Initial_Board_Reference: MBxxxx; Component_Country_Of_Origin: China; ID: 2796; ShowFields: YES
R65-R67 R85 = MCD-00053: Resistor,10K,0402,1%,1/16W; Manufacturer_Part_Number: RC0402FR-0710KL; Manufacturer: YAGEO; BMS_Part_Number: 9131590; Part_Preference: Recommended; Provided_By: SUBCO; Component_Country_Of_Origin: China; ID: 2539; Order_Code_RS: 9239359; ShowFields: YES
R68 R75 = MCD-00052: as R97 on sheet JTAG
R71 = MCD-00185: Resistor,3K,0402,1%,1/16W; Manufacturer_Part_Number: RC0402FR-073KL; Manufacturer: YAGEO; Part_Preference: Recommended; Provided_By: SUBCO; Component_Country_Of_Origin: China; ID: 2682; ShowFields: YES
R86 = MCD-00409: Resistor, 1K8, 0402, +/-1%, 1/16W; Part_Preference: Recommended; Manufacturer: YAGEO; Manufacturer_Part_Number: RC0402FR-071K8L; Component_Country_Of_Origin: China; ID: 2871; ShowFields: YES
R87 = MCD-00185: Resistor, 3K, 0402, +/-1%, 1/16W; Part_Preference: Recommended; Manufacturer: YAGEO; Manufacturer_Part_Number: RC0402FR-073KL; Component_Country_Of_Origin: China; ID: 2682; ShowFields: YES
R128 = MCD-00381: Resistor, 1K3, 0402, +/-1%, 1/16W; Part_Preference: Recommended; Manufacturer: YAGEO; Manufacturer_Part_Number: RC0402FR-071K3L; Component_Country_Of_Origin: China; ShowFields: YES; ID: 2898
R129 = MCD-02455: Resistor, 3K9, 0402, +/-1%, 1/16W, +/-100ppm/°C; Part_Preference: Recommended; Manufacturer: YAGEO; Manufacturer_Part_Number: RC0402FR-073K9L; Order_Code_RS: 198-7783; Component_Country_Of_Origin: China; ShowFields: YES; ID: 4561
TP13 = MCD-00074: Test Point 1mm; Part_Type: Misc; Part_Preference: Recommended; Component_Country_Of_Origin: Unknown; ID: 2518; ShowFields: YES
U3 U4 = MCD-00136: Dual Transil array for ESD protection; BMS_Part_Number: 9151112; Part_Type: Diode; Part_Preference: Recommended; Manufacturer: STMICROELECTRONICS; Manufacturer_HQ_COO: EU; Component_Country_Of_Origin: China; ID: 2731; Order_Code_RS: 178-7373; ShowFields: YES
U13 = MCD-01207: High power Transient voltage suppressor:25V/35A EOS and ESD transients protection.; Part_Type: Diode; Manufacturer: STMICROELECTRONICS; BMS_Part_Number: 9179045; Manufacturer_HQ_COO: EU; Part_Preference: Recommended; ECCN_US: EAR99; ECCN_EU: NEC; Provided_By: SUBCO with ST control; Component_Country_Of_Origin: China; ID: 3289; Order_Code_RS: 163-9774; ShowFields: YES
U19 = MCD-00649: Common mode filter with ESD protection for USB 2.0 interface; BMS_Part_Number: 9151138; Part_Type: Diode; Part_Preference: Recommended; Manufacturer: STMICROELECTRONICS; Manufacturer_HQ_COO: EU; Component_Country_Of_Origin: China; ShowFields: YES; ID: 3094; Order_Code_RS: 880-5276
U21 = MCD-00159: 500mA, Enhanced single channel power switches with active high enable pin; BMS_Part_Number: 9159009; Part_Type: IC; Part_Preference: Recommended; Manufacturer: STMICROELECTRONICS; Component_Country_Of_Origin: Malaysia; ShowFields: YES; ID: 2708; Order_Code_RS: 165-5516
U22 = MCD-02706: STM32F723IEK  (STM32F7) BGA176; BMS_Part_Number: 9175300; Part_Type: IC; Part_Preference: Not recommended; Manufacturer: STMICROELECTRONICS; Order_Code_RS: 135-8241; ShowFields: YES; ID: 4812
U24 = MCD-02514: LDO, 3.3V, 300mA, High input voltage: 2.5V to 28V, SOT23-5L; Part_Type: IC; Part_Preference: Recommended; Manufacturer: STMICROELECTRONICS; Component_Country_Of_Origin: Malaysia; ID: 4620; ShowFields: YES
U26 U27 = MCD-01945: 4-bit dual supply translating transceiver with configurable voltage translation; 3-state; Part_Type: IC; Manufacturer: NEXPERIA; Part_Preference: Recommended; Full_Alternate_Internal_Part_Number: MCD-03085; Component_Country_Of_Origin: Thailand; ID: 4045; ShowFields: YES
U34 = MCD-02532: eFuse with Fast Overvoltage Protection 2.7V to 18V 4A 34mOhm 8-Pin WSON; Part_Type: IC; Part_Preference: Recommended; Manufacturer: TEXAS INSTRUMENTS; Component_Country_Of_Origin: Thailand; ID: 4638; ShowFields: YES
X1 = MCD-01036: Crystal, 24MHz, 6pF, +/-20ppm, 80R, 2x1.6mm; BMS_Part_Number: 9157045; Part_Type: Crystal_Osc; Part_Preference: Recommended; Manufacturer: NDK; Manufacturer_Part_Number: NX2016SA-24MHZ-EXS00A-CS10820; Component_Country_Of_Origin: Unknown; ID: 2989; ShowFields: YES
